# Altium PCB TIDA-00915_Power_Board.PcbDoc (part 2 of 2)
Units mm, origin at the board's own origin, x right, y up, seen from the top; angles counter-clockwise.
Board outline 80 x 46 mm, 3 copper layers (Top Layer, Signal Layer 1, Base Aluminium), stack 1.964 mm thick; 95 components, 53 nets, 450 pads, 406 vias.
Unrouted connection lines stored in the file: 2.
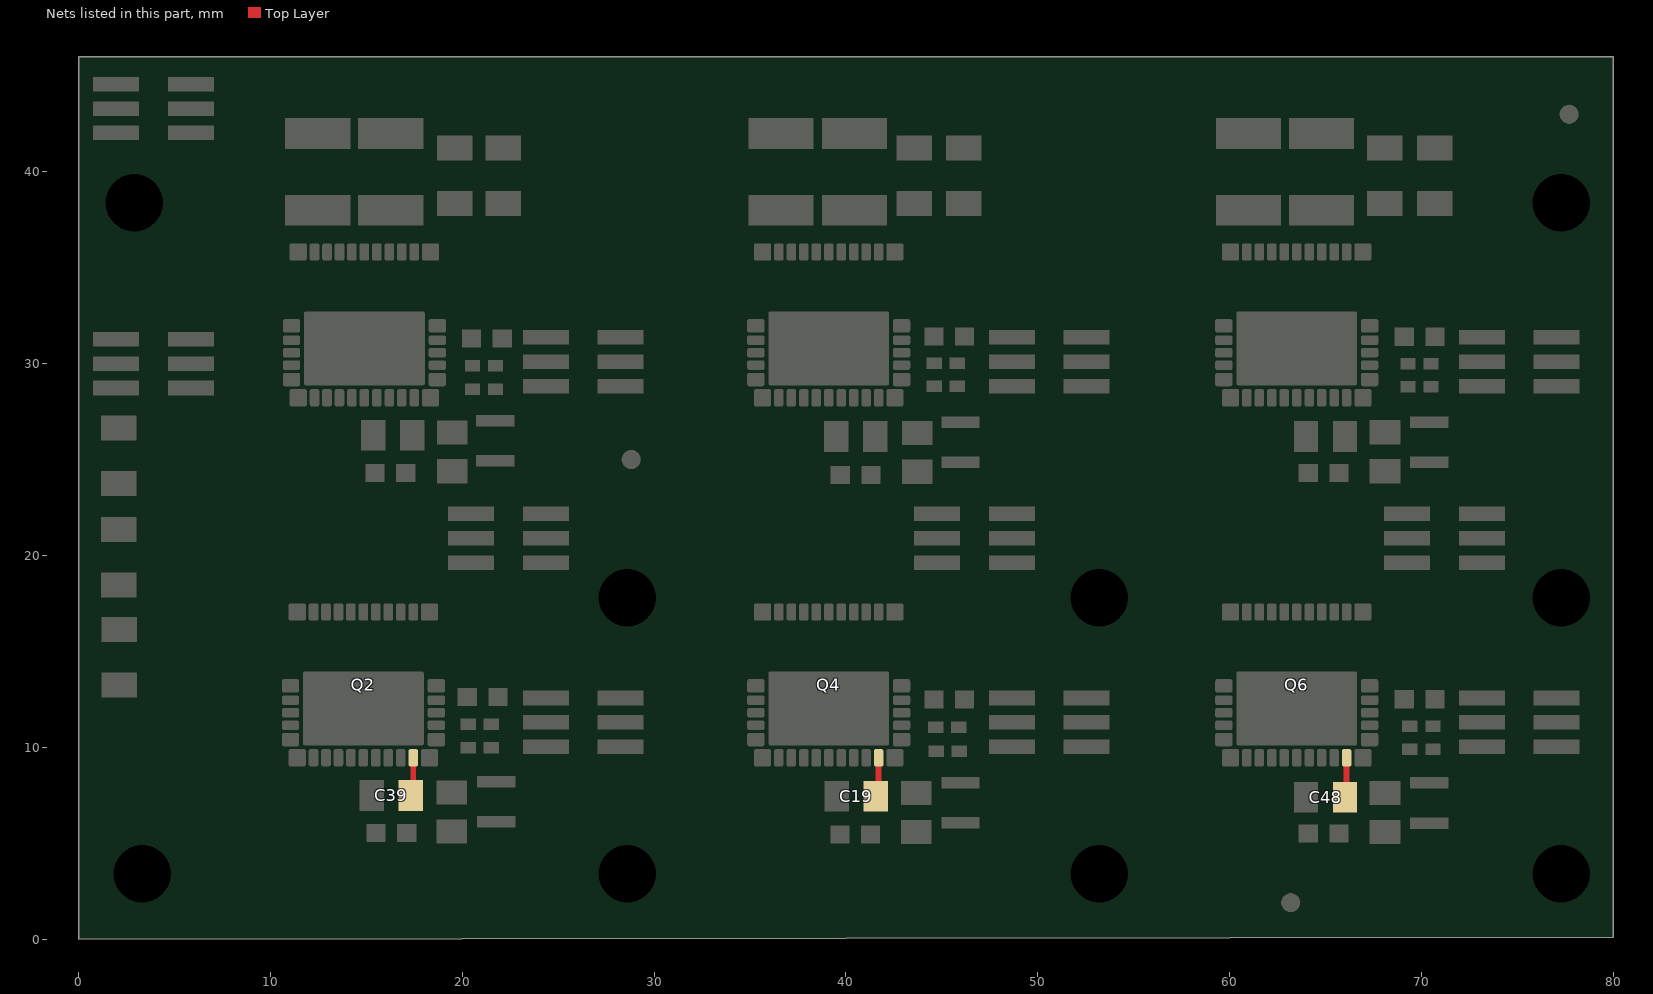
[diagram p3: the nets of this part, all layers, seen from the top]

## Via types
v1: diameter 0.559, hole 0.305, Top Layer to Signal Layer 1, 282 vias
v2: diameter 0.61, hole 0.305, Top Layer to Signal Layer 1, 118 vias
v3: diameter 0.8, hole 0.4, Top Layer to Signal Layer 1, 6 vias

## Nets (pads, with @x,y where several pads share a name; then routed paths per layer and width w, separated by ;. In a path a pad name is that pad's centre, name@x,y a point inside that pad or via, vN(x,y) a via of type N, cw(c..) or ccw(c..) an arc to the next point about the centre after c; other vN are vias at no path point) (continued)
VM12V_L_U: C39.1 Q2.26 | length 2
  Top Layer w0.203: C39.1@17.316,7.491 C39.1@17.439,7.614
  Top Layer w0.305: C39.1@17.439,7.614 Q2.26@17.439,9.452
VM12V_L_V: C19.1 Q4.26 | length 2.1
  Top Layer w0.305: C19.1@41.549,7.441 41.7,7.591 Q4.26@41.7,9.452
VM12V_L_W: C48.1 Q6.26 | length 2.1
  Top Layer w0.305: C48.1@66.016,7.4 66.1,7.484 Q6.26@66.1,9.452
pads on no net: FID1.1 FID2.1 FID3.1 Q1.33@12.512,29.908 Q1.33@12.512,31.708 Q1.33@13.702,29.908 Q1.33@13.702,31.708 Q1.33@14.892,29.908 Q1.33@14.892,31.708 Q1.33@16.082,29.908 Q1.33@16.082,31.708 Q1.33@17.272,29.908 Q1.33@17.272,31.708 Q2.33@12.459,11.138 Q2.33@12.459,12.938 Q2.33@13.649,11.138 Q2.33@13.649,12.938 Q2.33@14.839,11.138 Q2.33@14.839,12.938 Q2.33@16.029,11.138 Q2.33@16.029,12.938 Q2.33@17.219,11.138 Q2.33@17.219,12.938 Q3.33@36.72,29.908 Q3.33@36.72,31.708 Q3.33@37.91,29.908 Q3.33@37.91,31.708 Q3.33@39.1,29.908 Q3.33@39.1,31.708 Q3.33@40.29,29.908 Q3.33@40.29,31.708 Q3.33@41.48,29.908 Q3.33@41.48,31.708 Q4.33@36.72,11.138 Q4.33@36.72,12.938 Q4.33@37.91,11.138 Q4.33@37.91,12.938 Q4.33@39.1,11.138 Q4.33@39.1,12.938 Q4.33@40.29,11.138 Q4.33@40.29,12.938 Q4.33@41.48,11.138 Q4.33@41.48,12.938 Q5.33@61.12,29.908 Q5.33@61.12,31.708 Q5.33@62.31,29.908 Q5.33@62.31,31.708 Q5.33@63.5,29.908 Q5.33@63.5,31.708 Q5.33@64.69,29.908 Q5.33@64.69,31.708 Q5.33@65.88,29.908 Q5.33@65.88,31.708 Q6.33@61.12,11.138 Q6.33@61.12,12.938 Q6.33@62.31,11.138 Q6.33@62.31,12.938 Q6.33@63.5,11.138 Q6.33@63.5,12.938 Q6.33@64.69,11.138 Q6.33@64.69,12.938 Q6.33@65.88,11.138 Q6.33@65.88,12.938

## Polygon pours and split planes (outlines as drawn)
PHASEW on Top Layer "TOP_LAYER_PHASEW_P170" (solid, remove dead copper, pour order 170): 71.619,29.716 ccw(c71.619,29.553) 71.455,29.553 71.455,28.561 cw(c71.295,28.561) 71.295,28.4 70.894,28.396 cw(c70.879,28.471) 70.879,28.395 70.523,28.395 cw(c70.523,28.674) 70.244,28.674 70.244,31.524 cw(c70.468,31.524) 70.468,31.748 71.082,31.748 cw(c71.082,31.468) 71.361,31.468 71.361,30.591 ccw(c71.551,30.591) 71.551,30.402 71.92,30.402 cw(c71.92,30.164) 72.158,30.164 72.158,29.905 cw(c71.969,29.905) 71.969,29.716
PHASEV on Top Layer "TOP_LAYER_PHASEV_P168" (solid, remove dead copper, pour order 168): 47.219,29.716 ccw(c47.219,29.553) 47.055,29.553 47.055,28.561 cw(c46.895,28.561) 46.895,28.4 46.494,28.396 cw(c46.479,28.471) 46.479,28.395 46.123,28.395 cw(c46.123,28.674) 45.844,28.674 45.844,31.524 cw(c46.068,31.524) 46.068,31.748 46.682,31.748 cw(c46.682,31.468) 46.961,31.468 46.961,30.591 ccw(c47.151,30.591) 47.151,30.402 47.52,30.402 cw(c47.52,30.164) 47.758,30.164 47.758,29.905 cw(c47.569,29.905) 47.569,29.716
HVBUS_RTN on Top Layer "TOP_LAYER_HVBUS_RTN_P162" (solid, remove dead copper, pour order 162): 59.216,4.087 ccw(c59.803,4.087) 59.803,3.501 71.208,3.501 ccw(c71.203,4.03) 71.732,4.034 ccw(c71.37,4.106) 71.739,4.106 71.739,5.873 ccw(c71.395,5.873) 71.395,6.217 67.409,6.217 ccw(c67.409,6.09) 67.283,6.09 67.283,4.869 cw(c67.068,4.869) 67.068,4.654 64.737,4.654 cw(c64.737,5.006) 64.384,5.006 64.384,8.448 cw(c64.644,8.448) 64.644,8.708 ccw(c64.644,8.837) 64.774,8.837 64.774,13.477 ccw(c64.344,13.477) 64.344,13.906 56.892,13.906 ccw(c56.892,13.637) 56.622,13.637 56.622,8.963 ccw(c56.794,8.963) 56.794,8.792 59.089,8.792 cw(c59.089,8.664) 59.216,8.664
PHASEW on Top Layer "TOP_LAYER_PHASEW_P158" (solid, remove dead copper, pour order 158): 63.75,22.76 cw(c63.75,23.066) 63.445,23.066 63.445,28.894 cw(c63.553,28.901) 63.546,29.01 64.635,29.01 cw(c64.635,28.773) 64.873,28.773 64.873,28.017 cw(c64.669,28.017) 64.669,27.813 64.531,27.813 ccw(c64.531,27.597) 64.314,27.597 64.314,23.841 ccw(c64.627,23.841) 64.627,23.528 67.236,23.528 ccw(c67.236,23.819) 67.528,23.819 67.528,24.758 cw(c67.744,24.758) 67.744,24.975 71.611,24.975 cw(c71.611,24.868) 71.718,24.868 71.718,23.152 cw(c71.326,23.152) 71.326,22.76
PHASEW on Top Layer "TOP_LAYER_PHASEW_P156" (solid, remove dead copper, pour order 156): 62.99,27.76 ccw(c62.99,27.559) 62.789,27.559 62.789,22.891 ccw(c63.185,22.891) 63.185,22.496 73.819,22.496 cw(c73.819,22.365) 73.95,22.365 73.95,18.741 cw(c73.8,18.741) 73.8,18.591 69.928,18.596 cw(c69.916,18.795) 69.915,18.596 67.805,18.596 ccw(c67.805,18.367) 67.576,18.367 67.568,16.688 cw(c67.468,16.696) 67.468,16.596 60.168,16.596 59.507,16.609 cw(c59.507,16.863) 59.253,16.863 59.253,32.561 cw(c59.421,32.561) 59.421,32.728 61.423,32.728 ccw(c61.445,32.728) 61.445,32.706 63.592,32.706 cw(c63.594,32.538) 63.762,32.54 63.762,27.871 cw(c63.651,27.871) 63.651,27.76
PHASEV on Top Layer "TOP_LAYER_PHASEV_P154" (solid, remove dead copper, pour order 154): 39.924,27.534 cw(c40.138,27.534) 40.138,27.748 40.665,27.748 ccw(c40.665,27.798) 40.716,27.798 40.716,28.934 ccw(c40.639,28.934) 40.639,29.01 40.246,29.01 38.954,29.01 ccw(c38.954,28.91) 38.854,28.91 38.854,23.249 ccw(c39.343,23.249) 39.343,22.76 46.937,22.76 ccw(c46.937,23.152) 47.329,23.152 47.329,24.868 ccw(c47.222,24.868) 47.222,24.975 43.355,24.975 ccw(c43.355,24.758) 43.138,24.758 43.138,23.819 cw(c42.847,23.819) 42.847,23.528 40.237,23.528 cw(c40.237,23.841) 39.924,23.841
HVBUS_RTN on Top Layer "TOP_LAYER_HVBUS_RTN_P148" (solid, remove dead copper, pour order 148): 32.23,13.957 ccw(c32.23,13.863) 32.136,13.863 32.136,9.031 ccw(c32.346,9.031) 32.346,8.822 34.578,8.822 cw(c34.578,8.643) 34.756,8.643 34.756,4.387 ccw(c35.356,4.387) 35.356,3.787 46.909,3.787 ccw(c46.909,4.157) 47.279,4.157 47.279,5.923 ccw(c46.935,5.923) 46.935,6.267 42.949,6.267 ccw(c42.949,6.141) 42.823,6.141 42.823,4.92 cw(c42.608,4.92) 42.608,4.704 40.277,4.704 cw(c40.277,5.057) 39.924,5.057 39.924,8.499 cw(c40.184,8.499) 40.184,8.759 ccw(c40.184,8.888) 40.314,8.888 40.314,13.527 ccw(c39.884,13.527) 39.884,13.957
PHASEV on Top Layer "TOP_LAYER_PHASEV_P146" (solid, remove dead copper, pour order 146): 38.324,27.79 ccw(c38.324,27.743) 38.278,27.743 38.278,22.841 ccw(c38.623,22.841) 38.623,22.496 49.504,22.496 cw(c49.504,22.3) 49.7,22.3 49.7,18.8 cw(c49.5,18.8) 49.5,18.6 45.366,18.596 cw(c45.354,18.795) 45.354,18.596 43.243,18.596 ccw(c43.243,18.367) 43.014,18.367 43.006,16.688 cw(c42.906,16.696) 42.906,16.596 35.137,16.596 cw(c35.137,16.863) 34.869,16.863 34.869,32.471 cw(c35.122,32.471) 35.122,32.724 35.26,32.724 cw(c35.305,32.498) 35.305,32.728 36.861,32.728 ccw(c36.883,32.728) 36.883,32.706 39.03,32.706 cw(c39.032,32.538) 39.2,32.54 39.2,28.295 39.2,27.9 cw(c39.091,27.9) 39.091,27.79
PHASEU on Top Layer "TOP_LAYER_PHASEU_P132" (solid, remove dead copper, pour order 132): 15.536,27.568 cw(c15.75,27.568) 15.75,27.781 16.276,27.781 ccw(c16.276,27.832) 16.327,27.832 16.327,28.968 ccw(c16.251,28.968) 16.251,29.044 15.857,29.044 14.566,29.044 ccw(c14.566,28.943) 14.465,28.943 14.465,23.283 ccw(c14.955,23.283) 14.955,22.794 22.548,22.794 ccw(c22.548,23.186) 22.94,23.186 22.94,24.901 ccw(c22.833,24.901) 22.833,25.008 18.966,25.008 ccw(c18.966,24.792) 18.75,24.792 18.75,23.853 cw(c18.458,23.853) 18.458,23.562 15.849,23.562 cw(c15.849,23.874) 15.536,23.874
HVBUS_RTN on Top Layer "TOP_LAYER_HVBUS_RTN_P058" (solid, remove dead copper, pour order 58): 70.6,12.975 ccw(c70.6,12.751) 70.376,12.751 70.376,9.902 ccw(c70.656,9.902) 70.656,9.622 71.011,9.622 ccw(c71.011,9.698) 71.087,9.698 71.087,10.714 cw(c71.316,10.714) 71.316,10.943 72.101,10.943 ccw(c72.101,11.132) 72.29,11.132 72.29,11.391 ccw(c72.053,11.391) 72.053,11.629 71.683,11.629 cw(c71.683,11.818) 71.494,11.818 71.494,12.696 ccw(c71.214,12.696) 71.214,12.975
HVBUS_RTN on Top Layer "TOP_LAYER_HVBUS_RTN_P052" (solid, remove dead copper, pour order 52): 46.06,12.953 ccw(c46.06,12.73) 45.837,12.73 45.837,9.88 ccw(c46.116,9.88) 46.116,9.601 46.472,9.601 ccw(c46.472,9.677) 46.548,9.677 46.548,10.693 cw(c46.776,10.693) 46.776,10.921 47.562,10.921 ccw(c47.562,11.111) 47.751,11.111 47.751,11.369 ccw(c47.513,11.369) 47.513,11.607 47.144,11.607 cw(c47.144,11.797) 46.954,11.797 46.954,12.674 ccw(c46.675,12.674) 46.675,12.953
HVBUS_RTN on Top Layer "HVBUS_RTN_MAIN" (solid, remove dead copper, pour order 38): 71.474,45 cw(c71.474,44.871) 71.602,44.871 71.602,41.152 cw(c71.45,41.152) 71.45,41 69.759,41.006 cw(c69.7,41.3) 69.7,41 10.1,41 cw(c10.1,41.2) 9.9,41.2 9.9,41.5 ccw(c9.7,41.5) 9.7,41.7 1.2,41.7 cw(c1.2,42) 0.9,42 0.9,44.5 cw(c1.4,44.5) 1.4,45 9.8,45
HVBUS on Top Layer "HVBUS_MAIN" (solid, remove dead copper, pour order 40): 8.971,35.5 ccw(c8.971,35.254) 8.726,35.254 8.726,28.793 cw(c8.469,28.795) 8.467,28.538 cw(c8.4,29.222) 8.4,28.535 1.15,28.535 cw(c1.15,28.885) 0.8,28.885 0.8,34.298 cw(c1.524,34.298) 1.524,35.022 6.063,35.022 ccw(c6.063,35.459) 6.5,35.459 6.5,38.4 cw(c6.798,38.398) 6.8,38.696 7.861,38.696 cw(c7.899,38.508) 7.9,38.7 69.663,38.7 69.663,38.696 71.404,38.696 cw(c71.404,38.524) 71.411,38.696 cw(c71.411,38.461) 71.646,38.461 71.646,35.597 cw(c71.549,35.597) 71.549,35.5
PHASEU on Top Layer "TOP_LAYER_PHASEU_P044" (solid, remove dead copper, pour order 44): 23.011,29.716 ccw(c23.011,29.553) 22.847,29.553 22.847,28.561 cw(c22.687,28.561) 22.687,28.4 22.286,28.396 cw(c22.271,28.471) 22.271,28.395 21.915,28.395 cw(c21.915,28.674) 21.636,28.674 21.636,31.524 cw(c21.86,31.524) 21.86,31.748 22.474,31.748 cw(c22.474,31.468) 22.753,31.468 22.753,30.591 ccw(c22.943,30.591) 22.943,30.402 23.312,30.402 cw(c23.312,30.164) 23.55,30.164 23.55,29.905 cw(c23.361,29.905) 23.361,29.716
PHASEU on Top Layer "TOP_LAYER_PHASEU_P120" (solid, remove dead copper, pour order 120): 24.7,18.6 24.75,18.6 ccw(c24.75,19) 25.15,19 25.15,22.209 ccw(c24.859,22.209) 24.86,22.5 14.15,22.5 cw(c14.15,22.65) 14,22.65 14,27.572 cw(c14.4,27.572) 14.4,27.972 ccw(c14.4,28.299) 14.727,28.299 14.727,32.544 ccw(c14.559,32.542) 14.557,32.71 12.41,32.71 cw(c12.41,32.733) 12.388,32.733 10.833,32.733 ccw(c10.833,32.5) 10.6,32.5 10.6,16.813 ccw(c10.813,16.813) 10.813,16.6 18.433,16.6 ccw(c18.433,16.7) 18.533,16.692 18.541,18.371 cw(c18.77,18.371) 18.77,18.6 20.73,18.6
HVBUS_RTN on Top Layer "TOP_LAYER_HVBUS_RTN_P126" (solid, remove dead copper, pour order 126): 22.738,11.016 ccw(c22.738,10.853) 22.574,10.853 22.574,9.861 cw(c22.414,9.861) 22.414,9.7 22.013,9.696 cw(c21.998,9.771) 21.998,9.695 21.642,9.695 cw(c21.642,9.974) 21.363,9.974 21.363,12.824 cw(c21.587,12.824) 21.587,13.048 22.201,13.048 cw(c22.201,12.768) 22.48,12.768 22.48,11.891 ccw(c22.67,11.891) 22.67,11.702 23.039,11.702 cw(c23.039,11.464) 23.277,11.464 23.277,11.205 cw(c23.088,11.205) 23.088,11.016
HVBUS_RTN on Top Layer "TOP_LAYER_HVBUS_RTN_P130" (solid, remove dead copper, pour order 130): 10.582,3.882 ccw(c10.947,3.882) 10.947,3.516 22.421,3.516 ccw(c22.421,4.2) 23.105,4.2 23.105,5.967 ccw(c22.761,5.967) 22.761,6.311 18.775,6.311 ccw(c18.775,6.184) 18.649,6.184 18.649,4.963 cw(c18.434,4.963) 18.434,4.748 16.102,4.748 cw(c16.102,5.1) 15.75,5.1 15.75,8.542 cw(c16.01,8.542) 16.01,8.802 ccw(c16.01,8.931) 16.139,8.931 16.139,13.571 ccw(c15.71,13.571) 15.71,14 7.771,14 ccw(c7.771,13.829) 7.6,13.829 7.6,8.906 ccw(c7.82,8.906) 7.82,8.686 10.438,8.686 cw(c10.438,8.542) 10.582,8.542
PHASEU on Signal Layer 1 "SIGNAL_LAYER_1_PHASEU_P128" (solid, remove dead copper, pour order 128): 29.624,33.6 cw(c29.624,33.43) 29.794,33.43 29.794,22.661 cw(c29.616,22.661) 29.616,22.483 28.715,22.527 15.362,22.527 14.6,22.53 cw(c14.6,22.888) 14.242,22.888 14.242,28.222 cw(c14.376,28.222) 14.376,28.356 18.6,28.356 ccw(c18.6,28.698) 18.942,28.698 18.942,32.227 18.942,33.5 cw(c19.042,33.5) 19.042,33.6
PHASEU on Signal Layer 1 "SIGNAL_LAYER_1_PHASEU_P116" (solid, remove dead copper, pour order 116): 14.947,32.695 14.608,32.695 ccw(c14.608,32.409) 14.322,32.409 14.322,28.978 ccw(c14.625,28.978) 14.625,28.674 15.002,28.674 ccw(c15.002,28.7) 15.028,28.7 18.479,28.7 ccw(c18.478,28.974) 18.752,28.974 18.752,32.409 ccw(c18.461,32.409) 18.461,32.7 15,32.7 ccw(c15,32.428)
no net on Signal Layer 1 "SIGNAL_LAYER_1_NONET_P068" (solid, remove dead copper, pour order 68): 21.096,44.96
no net on Signal Layer 1 "SIGNAL_LAYER_1_NONET_P088" (solid, remove dead copper, pour order 88): 12.828,28.29
no net on Signal Layer 1 "SIGNAL_LAYER_1_NONET_P090" (solid, remove dead copper, pour order 90): 13.628,28.311
no net on Signal Layer 1 "SIGNAL_LAYER_1_NONET_P096" (solid, remove dead copper, pour order 96): 19.182,11.9 19.241,11.959 19.241,12
PHASEV on Signal Layer 1 "SIGNAL_LAYER_1_PHASEV_P134" (solid, remove dead copper, pour order 134): 39.204,32.746 38.865,32.746 ccw(c38.865,32.46) 38.579,32.46 38.579,29.029 ccw(c38.882,29.029) 38.882,28.725 39.259,28.725 ccw(c39.259,28.751) 39.285,28.751 42.736,28.751 ccw(c42.735,29.025) 43.009,29.025 43.009,32.46 ccw(c42.718,32.46) 42.718,32.751 39.257,32.751 ccw(c39.257,32.479)
PHASEV on Signal Layer 1 "SIGNAL_LAYER_1_PHASEV_P136" (solid, remove dead copper, pour order 136): 38.734,28.254 ccw(c38.734,28.12) 38.601,28.12 38.601,22.787 ccw(c38.959,22.787) 38.959,22.429 39.721,22.426 53.144,22.426 ccw(c53.144,23.041) 53.759,23.041 53.759,32.326 ccw(c53.559,32.326) 53.725,32.437 53.725,33.145 ccw(c53.372,33.145) 53.372,33.498 43.401,33.498 ccw(c43.401,33.398) 43.301,33.398 43.301,32.126 43.301,28.596 cw(c42.959,28.596) 42.959,28.254
PHASEW on Signal Layer 1 "SIGNAL_LAYER_1_PHASEW_P140" (solid, remove dead copper, pour order 140): 63.639,32.746 63.3,32.746 ccw(c63.3,32.46) 63.014,32.46 63.014,29.029 ccw(c63.317,29.029) 63.317,28.725 63.694,28.725 ccw(c63.694,28.751) 63.72,28.751 67.171,28.751 ccw(c67.17,29.025) 67.444,29.025 67.444,32.46 ccw(c67.153,32.46) 67.153,32.751 63.692,32.751 ccw(c63.692,32.479)
HVBUS_RTN on Signal Layer 1 "SIGNAL_LAYER_1_HVBUS_RTN_P142" (solid, remove dead copper, pour order 142): 36.9,16.096 ccw(c37.5,16.096) 37.5,15.497 42.023,15.497 cw(c42.042,14.981) 42.558,15 42.558,10.349 cw(c42.258,10.349) 42.258,10.049 32.634,10.049 cw(c32.65,10.563) 32.136,10.578 32.136,44.247 cw(c32.736,44.247) 32.736,44.846 46.8,44.846 cw(c46.8,44.178) 47.468,44.178 47.468,36.922 cw(c47.201,36.922) 47.2,36.654 43.627,36.654 ccw(c43.627,36.219) 43.192,36.219 43.192,35.849 cw(c42.761,35.849) 42.761,35.418 37.269,35.418 ccw(c37.269,35.049) 36.9,35.049
HVBUS_RTN on Signal Layer 1 "SIGNAL_LAYER_1_HVBUS_RTN_P122" (solid, remove dead copper, pour order 122): 12.7,15.869 ccw(c13.069,15.869) 13.069,15.5 18.003,15.5 cw(c17.985,15.128) 18.357,15.111 18.357,10.4 cw(c18.057,10.4) 18.057,10.1 8.098,10.1 cw(c8.088,10.588) 7.6,10.579 7.6,44.675 cw(c7.822,44.675) 7.822,44.897 22.6,44.897 cw(c22.6,44.229) 23.268,44.229 23.268,36.973 cw(c23,36.973) 23,36.705 19.427,36.705 ccw(c19.427,36.27) 18.992,36.27 18.992,35.9 cw(c18.561,35.9) 18.561,35.469 13.069,35.469 ccw(c13.069,35.1) 12.7,35.1
HVBUS_RTN on Signal Layer 1 "SIGNAL_LAYER_1_HVBUS_RTN_P150" (solid, pour order 150): 54.4,7.4 cw(c54.2,7.4) 54.2,7.2 50.227,7.2 ccw(c50.227,6.8) 49.827,6.8 49.827,4.651 cw(c49,4.651) 49,3.824 39.598,3.824 35.317,3.827 32.509,3.827 cw(c32.509,4.2) 32.136,4.2 32.136,10.621 cw(c32.532,10.621) 32.532,11.017 41.917,11.017 41.917,13.628 cw(c42.193,13.629) 41.917,13.631 41.917,14.361 cw(c42.134,14.361) 42.134,14.577 54.306,14.577 cw(c54.306,14.483) 54.4,14.483
HVBUS_RTN on Signal Layer 1 "SIGNAL_LAYER_1_HVBUS_RTN_P152" (solid, pour order 152): 29.77,7.57 cw(c29.4,7.57) 29.4,7.2 24.95,7.2 ccw(c24.95,6.6) 24.35,6.6 cw(c24.35,6.55) 24.4,6.55 24.4,3.7 cw(c24.216,3.7) 24.216,3.516 24,3.513 15.064,3.513 10.782,3.516 7.975,3.516 cw(c7.975,3.889) 7.602,3.889 7.602,10.311 cw(c7.998,10.311) 7.998,10.707 17.382,10.707 17.382,13.318 cw(c17.659,13.318) 17.382,13.321 17.382,14.482 cw(c17.6,14.482) 17.6,14.7 29.57,14.7 cw(c29.57,14.5) 29.77,14.5
PHASEW on Signal Layer 1 "SIGNAL_LAYER_1_PHASEW_P138" (solid, remove dead copper, pour order 138): 63.322,28.203 ccw(c63.322,28.07) 63.188,28.07 63.188,22.736 ccw(c63.546,22.736) 63.546,22.378 64.308,22.375 77.731,22.375 ccw(c77.731,22.99) 78.346,22.99 78.346,32.275 ccw(c78.146,32.275) 78.312,32.386 78.312,33.095 ccw(c77.959,33.095) 77.959,33.448 67.988,33.448 ccw(c67.988,33.348) 67.888,33.348 67.888,32.075 67.888,28.545 cw(c67.546,28.545) 67.546,28.203
HVBUS_RTN on Signal Layer 1 "SIGNAL_LAYER_1_HVBUS_RTN_P160" (solid, remove dead copper, pour order 160): 61.386,16.414 ccw(c62.2,16.414) 62.2,15.6 66.689,15.6 cw(c66.716,15.273) 67.043,15.3 67.043,10.451 cw(c66.743,10.451) 66.743,10.151 57.12,10.151 cw(c57.135,10.664) 56.622,10.68 56.622,44.348 cw(c57.221,44.348) 57.221,44.947 71.286,44.947 cw(c71.286,44.28) 71.954,44.28 71.954,37.024 cw(c71.686,37.024) 71.686,36.756 68.113,36.756 ccw(c68.113,36.321) 67.678,36.321 67.678,35.951 cw(c67.247,35.951) 67.247,35.52 61.755,35.52 ccw(c61.755,35.151) 61.386,35.151
HVBUS_RTN on Signal Layer 1 "SIGNAL_LAYER_1_HVBUS_RTN_P164" (solid, pour order 164): 78.6,8.191 cw(c77.9,8.191) 77.9,7.491 74.921,7.491 ccw(c74.921,6.5) 73.93,6.5 73.93,4.188 cw(c73.27,4.158) 73.3,3.498 64.084,3.498 59.803,3.501 56.995,3.501 cw(c56.995,3.874) 56.622,3.874 56.622,10.295 cw(c57.018,10.295) 57.018,10.691 66.403,10.691 66.403,13.302 cw(c66.679,13.302) 66.403,13.305 66.403,14.129 cw(c66.874,14.129) 66.874,14.6 78.483,14.6 cw(c78.483,14.483) 78.6,14.483

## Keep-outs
Keep-Out Layer:
  text ".Layer_Name" at -9.944,-51.406 h1.52

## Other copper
Top Layer:
  text ".Layer_Name" at -9.944,-51.406 h1.52
Base Aluminium:
  text ".Layer_Name" at -9.944,-51.406 h1.52

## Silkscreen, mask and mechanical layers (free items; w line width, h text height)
Top Overlay:
  circle w0.254: c2.9,38.4 r2.5
  circle w0.254: c53.2,3.4 r2.5
  circle w0.254: c28.6,3.4 r2.5
  circle w0.254: c77.3,3.4 r2.5
  circle w0.254: c77.3,38.4 r2.5
  circle w0.254: c77.3,17.8 r2.5
  circle w0.254: c53.2,17.8 r2.5
  circle w0.254: c28.6,17.8 r2.5
  circle w0.254: c3.3,3.4 r2.5
  text ".Layer_Name" at -9.944,-51.406 h1.52
Bottom Overlay:
  text ".Layer_Name" at -9.944,-51.406 h1.52
Top Paste:
  text ".Layer_Name" at -9.944,-51.406 h1.52
Bottom Paste:
  text ".Layer_Name" at -9.944,-51.406 h1.52
Top Solder:
  region: 55.773,38.45 55.773,36.95 58.573,36.95 58.573,38.45
  region: 31.5,38.5 31.5,37 34.3,37 34.3,38.5
  region: 7.088,38.5 7.088,36.1 10,36.1 10,38.5
  region: 56.775,12.88 56.775,8.88 59,8.88 59,12.88
  region: 32.375,12.95 32.375,8.95 34.6,8.95 34.6,12.95
  region: 7.975,12.9 7.975,8.9 10.2,8.9 10.2,12.9
  region: 59.911,22.1 59.911,19.1 64.924,19.1 64.924,22.1
  region: 35.479,22.1 35.479,19.1 40.492,19.1 40.492,22.1
  region: 11.339,22.1 11.339,19.1 16.353,19.1 16.353,22.1
  text ".Layer_Name" at -9.944,-51.406 h1.52
  text ".Layer_Name" at -9.944,-51.406 h1.52
Bottom Solder:
  text ".Layer_Name" at -9.944,-51.406 h1.52
Drill Guide:
  text ".Layer_Name" at -9.944,-51.406 h1.52
M1 Board Outline:
  lines w0.254: 0,0 80,0 80,46 0,46 0,0
M2 Board Dimensions:
  rectangle: -21.425,-39.76 -11.9,-36.585
  rectangle: -24.6,-36.585 -21.425,-33.41
  lines w0.178: -24.6,-36.585 0.8,-36.585 ; -21.425,-39.76 -21.425,-33.41 ; -18.25,-39.76 -18.25,-33.41 ; -11.9,-39.76 -11.9,-33.41 ; -5.55,-39.76 -5.55,-33.41 ; -24.6,-39.76 -24.6,-33.41 0.8,-33.41 0.8,-39.76 -24.6,-39.76
M3 3D STEP Top:
  text ".Layer_Name" at -9.944,-51.406 h1.52
M4 3D STEP Bottom:
  text ".Layer_Name" at -9.944,-51.406 h1.52
M5 Assembly Top:
  lines w0.254: -32.017,-53.226 135.623,-53.226 ; -32.017,-48.062 135.674,-48.062 ; -32.017,-42.897 -32.017,-58.391 69.71,-58.391 135.674,-58.391 135.674,-42.897 -32.004,-42.897 -32.004,-58.391 8.014,-58.391 ; 30.594,-58.391 30.594,-42.897 ; 62.776,-48.062 62.776,-42.897 ; 84.112,-48.062 84.112,-42.897 ; 99.911,-58.556 99.911,-53.404
  text "COMPONENTS MARKED 'DNP' SHOULD NOT BE POPULATED." at 4.699,-37.69 h1.52
  text "ASSEMBLY VARIANT:" at 4.686,-40.624 h1.52
  text ".VariantName" at 31.001,-40.624 h1.52
  text "PCB VIEWED FROM TOP SIDE" at -30.404,-46.254 h1.52
  text "BOARD #:" at 32.499,-46.254 h1.52
  text ".PRJ_Number" at 46.355,-46.254 h1.52
  text "REV:" at 67.805,-46.254 h1.52
  text ".PCB_Rev" at 75.209,-46.254 h1.52
  text "SVN REV:" at 89.09,-46.254 h1.52
  text ".VersionControl_RevNumber" at 101.943,-46.254 h1.52
  text "'.Layer_Name'" at -5.7,-51.3 h1.52
  text "TID #:" at 32.499,-51.419 h1.52
  text ".TID" at 46.355,-51.419 h1.52
  text "PLOT NAME =" at -30.404,-56.634 h1.52
  text ".plot_File_Name" at -9.944,-56.634 h1.52
  text "GENERATED    :" at 32.55,-56.634 h1.52
  text ".Print_Date" at 54.635,-56.634 h1.52
  text ".Print_Time" at 73.152,-56.634 h1.52
  text "TEXAS INSTRUMENTS" at 105.27,-56.634 h1.52
M6 Assembly Bottom:
  lines w0.254: -32.029,-48.074 135.661,-48.074 ; -31.979,-53.239 135.661,-53.239 ; 3.734,-58.569 3.734,-53.417 ; 19.533,-48.074 19.533,-42.91 ; 40.869,-48.074 40.869,-42.91 ; 73.05,-58.404 73.05,-42.91 ; 95.631,-58.404 135.649,-58.404 135.649,-42.91 -32.029,-42.91 -32.029,-58.404 33.934,-58.404 135.661,-58.404 135.661,-42.91
  text "COMPONENTS MARKED 'DNP' SHOULD NOT BE POPULATED." at 130.391,-37.677 h1.52
  text ".VariantName" at 103.873,-40.624 h1.52
  text "ASSEMBLY VARIANT:" at 130.264,-40.624 h1.52
  text ".VersionControl_RevNumber" at 1.702,-46.267 h1.52
  text "SVN REV:" at 14.554,-46.267 h1.52
  text ".PCB_Rev" at 28.435,-46.267 h1.52
  text "REV:" at 35.839,-46.267 h1.52
  text ".PRJ_Number" at 57.29,-46.267 h1.52
  text "BOARD #:" at 71.145,-46.267 h1.52
  text "PCB VIEWED FROM BOTTOM SIDE" at 134.048,-46.267 h1.52
  text ".TID" at 57.29,-51.431 h1.52
  text "TID #:" at 71.145,-51.431 h1.52
  text "'.Layer_Name'" at 101,-51.6 h1.52
  text "TEXAS INSTRUMENTS" at -1.626,-56.647 h1.52
  text ".Print_Time" at 30.493,-56.647 h1.52
  text ".Print_Date" at 49.009,-56.647 h1.52
  text "GENERATED    :" at 71.095,-56.647 h1.52
  text ".plot_File_Name" at 113.589,-56.647 h1.52
  text "PLOT NAME =" at 134.048,-56.647 h1.52
M9 Title Sheet:
  drawing of 57 lines, arcs and shapes, not listed
  text "1" at -5.808,174.527 h1.78
  text "2" at 57.582,174.527 h1.78
  text "3" at 120.811,174.527 h1.78
  text "4" at 184.48,174.527 h1.78
  text "5" at 247.955,174.527 h1.78
  text "6" at 311.582,174.527 h1.78
  text "A" at -35.179,145.495 h1.78
  text "A" at 340.741,145.495 h1.78
  text "B" at -35.179,85.043 h1.78
  text "B" at 340.741,85.043 h1.78
  text "C" at -35.179,24.718 h1.78
  text "C" at 340.741,24.718 h1.78
  text "PROJECT TITLE:" at 263.525,-22.551 h1.14
  text ".PRJ_Title" at 264.795,-25.938 h1.78
  text "DESIGNED FOR:" at 263.525,-30.197 h1.14
  text ".PRJ_Customer" at 264.795,-33.753 h1.78
  text "D" at -35.179,-35.48 h1.78
  text "D" at 340.741,-35.48 h1.78
  text "FILE NAME:" at 263.525,-37.817 h1.14
  text ".PCB_File_Name_No_Path" at 264.795,-40.865 h1.78
  text "Texas Instruments (TI) and/or its licensors do not warrant the accuracy or completeness of this specification" at 137.3,-44.976 h1.14
  text "ENGINEER:" at 263.525,-45.183 h1.14
  text "LAYOUT BY:" at 301.752,-45.183 h1.14
  text "or any information contained therein. TI and/or its licensors do not warrant that this design will meet" at 136.157,-47.837 h1.14
  text ".PRJ_Engineer" at 264.795,-49.12 h1.78
  text ".PCB_Layout" at 303.035,-49.12 h1.78
  text "the specifications, will be suitable for your application or fit for any particular purpose, or will operate in" at 136.157,-50.699 h1.14
  text "ALTIUM DESIGNER VERSION:" at 301.752,-53.057 h1.14
  text "an implementation. TI and/or its licensors do not warrant that the design is production worthy. You should" at 136.157,-53.561 h1.14
  text "completely validate and test your design implementation to confirm the system functionality for your application." at 137.3,-56.422 h1.14
  text ".print_Scale" at 264.795,-56.443 h1.78
  text ".Application_BuildNumber" at 303.035,-56.443 h1.78
  text "1" at -5.808,-61.693 h1.78
  text "2" at 57.582,-61.693 h1.78
  text "3" at 120.811,-61.693 h1.78
  text "4" at 184.48,-61.693 h1.78
  text "5" at 247.955,-61.693 h1.78
  text "6" at 311.582,-61.693 h1.78
M10 Fab Notes:
  drawing of 189 lines, arcs and shapes, not listed
  text "DESIGN INFORMATION" at 289.903,131.847 h1.52
  text "MIN. TRACK WIDTH:" at 273.531,128.491 h1.52
  text "8" at 301.376,128.491 h1.52
  text "MIL" at 305.307,128.491 h1.52
  text "MIN. CLEARANCE:" at 273.531,125.338 h1.52
  text "0.2" at 299.852,125.338 h1.52
  text "mm" at 305.307,125.338 h1.52
  text "MIN. VIA PAD SIZE:" at 273.531,122.185 h1.52
  text "24" at 300.614,122.185 h1.52
  text "MIL" at 305.307,122.185 h1.52
  text "0.05mm (2MIL)" at 291.184,118.886 h1.52
  text "MINIMUM ANNULAR RING" at 265.169,118.677 h1.52
  text "EXTERNAL" at 309.168,118.677 h1.52
  text "PER" at 270.249,115.88 h1.52
  text "IPC-D-275 CLASS 2 LEVEL C" at 275.837,115.88 h1.52
  text "MIL, HOLES" at 313.638,113.328 h1.52
  text "+/-" at 303.67,113.109 h1.52
  text "+/-" at 325.361,113.109 h1.52
  text "REGISTRATION TOLERANCES:" at 265.169,113.082 h1.52
  text "METAL" at 295.643,113.082 h1.52
  text "5" at 310.279,113.083 h1.52
  text "3" at 331.437,113.083 h1.52
  text "MIL" at 334.39,113.082 h1.52
  text "HOLE SIZE TOLERANCE (UNLESS OTHERWISE SPECIFIED):" at 265.169,110.585 h1.52
  text "+/-" at 325.361,110.512 h1.52
  text "3" at 331.437,110.485 h1.52
  text "MIL" at 334.39,110.485 h1.52
  text "MATERIAL:" at 263.27,106.989 h1.52
  text "FR-4 High Tg" at 288.326,103.724 h1.52
  text "FR-408" at 273.963,103.407 h1.52
  text "OTHER" at 311.758,103.407 h1.52
  text "62 MIL (1.6mm) +/-10%" at 282.094,99.774 h1.52
  text "THICKNESS:" at 265.169,99.565 h1.52
  text "OTHER" at 314.73,99.565 h1.52
  text "TOLERANCE:" at 265.169,96.052 h1.52
  text "ANSI IPC-6012 TYPE 3 CLASS 2" at 291.236,96.052 h1.52
  text "OTHER +/-" at 291.235,92.389 h1.52
  text "BOW & TWIST:" at 265.169,88.702 h1.52
  text "X" at 286.714,88.702 h1.52
  text "ANSI IPC-6012 TYPE 3 CLASS 2" at 291.236,88.702 h1.52
  text "OTHER +/-" at 291.235,84.976 h1.52
  text "DRILLING:" at 263.27,81.658 h1.52
  text "NC_DRILL FILES" at 307.999,78.986 h1.52
  text "REFERENCE:" at 265.169,78.886 h1.52
  text "X" at 281.863,78.884 h1.52
  text "AS SHOWN" at 286.384,78.886 h1.52
  text "X" at 304.748,78.886 h1.52
  text "OTHER" at 315.568,75.273 h1.52
  text "PTH COPPER THICKNESS:" at 265.161,75.183 h1.52
  text "X" at 294.097,75.183 h1.52
  text "20-30 um" at 297.348,75.183 h1.52
  text "BOARD FINISH:" at 263.27,71.434 h1.52
  text "SILKSCREEN:" at 267.213,68.637 h1.52
  text "X" at 291.54,68.637 h1.52
  text "TOP" at 294.512,68.637 h1.52
  text "X" at 304.494,68.637 h1.52
  text "BOTTOM" at 307.491,68.637 h1.52
  text "SILKSCREEN COLOR:" at 267.213,64.695 h1.52
  text "X" at 291.515,64.695 h1.52
  text "WHITE" at 294.512,64.695 h1.52
  text "OTHER" at 307.491,64.695 h1.52
  text "X" at 294.842,61.052 h1.52
  text "GREEN" at 297.839,61.052 h1.52
  text "OTHER" at 313.536,61.052 h1.52
  text "SOLDER RESIST COLOR:" at 267.213,60.877 h1.52
  text "X" at 294.842,57.134 h1.52
  text "MATTE" at 297.839,57.134 h1.52
  text "SEMI-GLOSS" at 313.525,57.117 h1.52
  text "IMMERSION GOLD (ENIG)" at 290.219,52.745 h1.52
  text "ENEPIG" at 324.193,52.562 h1.52
  text "SURFACE FINISH:" at 263.27,52.536 h1.52
  text "X" at 285.698,52.536 h1.52
  text "IMM. TIN/SILVER OR EQUIV" at 271.64,49.049 h1.52
  text "OTHER" at 307.999,48.949 h1.52
  text "ARRAY/PANEL:" at 263.27,45.002 h1.52
  text "CUT AND TRIM PER M1 BOARD OUTLINE" at 290.219,44.793 h1.52
  text "N.C. ROUTE" at 290.219,41.34 h1.52
  text "X" at 307.695,41.34 h1.52
  text "V. SCORE" at 312.216,41.34 h1.52
  text "CERTIFICATION:" at 263.27,38.06 h1.52
  text "MATERIALS AND WORKMANSHIP FOR ALL PCBS" at 281.685,38.06 h1.52
  text "TO MEET OR EXCEED THE REQUIREMENTS OF:" at 281.685,35.671 h1.52
  text "X" at 272.478,32.403 h1.52
  text "ANSI IPC-A-600F CLASS ->" at 275.729,32.403 h1.52
  text "X" at 317.588,32.403 h1.52
  text "2" at 320.382,32.403 h1.52
  text "1" at 312.381,32.365 h1.52
  text "3" at 329.373,32.365 h1.52
  text "X" at 293.102,28.652 h1.52
  text "RoHS" at 296.353,28.652 h1.52
  text "OTHER" at 312.721,28.652 h1.52
  text "PER ORDER" at 322.807,28.652 h1.52
  text "ALL BOARDS MUST MEET OR EXCEED UL94-V0 REQUIREMENTS." at 263.969,24.745 h1.52
  text "PCB MUST BEAR THE UL94V-0 UL REGISTERED MATERIAL ID NUMBER" at 263.969,21.797 h1.52
  text "NOTE:" at 108.214,18.101 h1.52
  text "ADDITIONAL REQUIREMENTS:" at 263.27,17.494 h1.52
  text "MICROSECTION:" at 265.169,14.773 h1.52
  text "YES" at 288.175,14.773 h1.52
  text "1)THIS IS NOT AN IMPEDANCE CONTROLLED BOARD." at 106.302,14.52 h1.52
  text "2)ALL VIAS ARE NONTENTED." at 106.133,11.598 h1.52
  text "REQUIRED" at 310.057,11.107 h1.52
  text "BARE BOARD ELEC. TEST:" at 265.169,11.034 h1.52
  text "NONE" at 298.335,11.034 h1.52
  text "X" at 307.06,11.034 h1.52
  text "PER ORDER" at 325.093,11.034 h1.52
  text "3)SELECTION OF DIELECRIC THICKNESS IS UP TO FAB VENDOR." at 106.233,8.698 h1.52
  text "XX MIL VIAS REQUIRE NON-CONDUCTIVE FILL AND PLANARIZE" at 269.44,5.828 h1.5
  text "4)COPPER THICKNESS SHOULD BE 2 OZ." at 105.706,5.725 h1.52
  text "XX MIL VIAS REQUIRE CONDUCTIVE FILL AND PLANARIZE" at 269.643,3.187 h1.52
  text "OUTER XX MIL TRACES REQUIRE 50 OHM SINGLE-ENDED IMPEDANCE" at 269.618,-0.963 h1.47
  text "LAYER 2 & 3 (INNER LAYERS) XX MIL WIDE, XX MIL SPACE / TRACES REQUIRE 100 OHM DIFFERENTIAL IMPEDANCE" at 269.415,-6.95 h1.52
M11 Gerber Information:
  lines w0.254: -32.017,-53.226 135.623,-53.226 ; -32.017,-48.062 135.674,-48.062 ; -32.017,-42.897 -32.017,-58.391 69.71,-58.391 135.674,-58.391 135.674,-42.897 -32.004,-42.897 -32.004,-58.391 8.014,-58.391 ; 30.594,-58.391 30.594,-42.897 ; 62.776,-48.062 62.776,-42.897 ; 84.112,-48.062 84.112,-42.897 ; 99.911,-58.556 99.911,-53.404
  text "ALL ARTWORK VIEWED FROM TOP SIDE" at -30.404,-46.254 h1.52
  text "BOARD #:" at 32.499,-46.254 h1.52
  text ".PRJ_Number" at 46.355,-46.254 h1.52
  text "REV:" at 67.805,-46.254 h1.52
  text ".PCB_Rev" at 75.209,-46.254 h1.52
  text "SVN REV:" at 89.09,-46.254 h1.52
  text ".VersionControl_RevNumber" at 101.943,-46.254 h1.52
  text "LAYER NAME =" at -30.404,-51.406 h1.52
  text "TID #:" at 32.499,-51.419 h1.52
  text ".TID" at 46.355,-51.419 h1.52
  text "PLOT NAME =" at -30.404,-56.634 h1.52
  text ".plot_File_Name" at -9.944,-56.634 h1.52
  text "GENERATED    :" at 32.55,-56.634 h1.52
  text ".Print_Date" at 54.635,-56.634 h1.52
  text ".Print_Time" at 73.152,-56.634 h1.52
  text "TEXAS INSTRUMENTS" at 105.27,-56.634 h1.52
M12 Stackup:
  drawing of 191 lines, arcs and shapes, not listed
  text "Layer" at 224.265,167.568 h1.52
  text "Name" at 234.677,167.568 h1.52
  text "Material" at 258.293,167.568 h1.52
  text "Thickness" at 280.131,167.568 h1.52
  text "Constant" at 296.636,167.568 h1.52
  text "Board Layer Stack" at 311.111,167.568 h1.52
  text "1" at 224.265,164.52 h1.52
  text "Top Overlay" at 234.677,164.52 h1.52
  text "2" at 224.265,161.472 h1.52
  text "Top Solder" at 234.677,161.472 h1.52
  text "Solder Resist" at 258.293,161.472 h1.52
  text "0.40mil" at 280.131,161.472 h1.52
  text "3.5" at 296.636,161.472 h1.52
  text "3" at 224.265,158.424 h1.52
  text "Top Layer" at 234.677,158.424 h1.52
  text "Copper" at 258.293,158.424 h1.52
  text "2.76mil" at 280.131,158.424 h1.52
  text "4" at 224.265,155.376 h1.52
  text "Dielectric1" at 234.677,155.376 h1.52
  text "Dielectric" at 258.293,155.376 h1.52
  text "5.98mil" at 280.131,155.376 h1.52
  text "3.4" at 296.636,155.376 h1.52
  text "5" at 224.265,152.328 h1.52
  text "Signal Layer 1" at 234.677,152.328 h1.52
  text "Copper" at 258.293,152.328 h1.52
  text "2.76mil" at 280.131,152.328 h1.52
  text "6" at 224.265,149.28 h1.52
  text "Dielectric 2" at 234.677,149.28 h1.52
  text "5.98mil" at 280.131,149.28 h1.52
  text "3.4" at 296.636,149.28 h1.52
  text "7" at 224.265,146.232 h1.52
  text "Base Aluminium" at 234.677,146.232 h1.52
  text "Copper" at 258.293,146.232 h1.52
  text "59.84mil" at 280.131,146.232 h1.52
M13 Component Bodies Top:
  text ".Layer_Name" at -9.944,-51.406 h1.52
M14 Component Bodies Bottom:
  text ".Layer_Name" at -9.944,-51.406 h1.52
M15 Courtyards Top:
  text ".Layer_Name" at -9.944,-51.406 h1.52
M16 Courtyards Bottom:
  text ".Layer_Name" at -9.944,-51.406 h1.52
Drill Drawing:
  circle w0.254: c111.262,49.687 r0.562
  lines w0.254: 110.7,51.655 111.824,51.655 111.824,52.78 110.7,52.78 110.7,51.655 ; 110.7,55.31 111.824,55.31 111.262,54.186 110.7,55.31
  lines w0.305: 109.664,48.366 190.525,48.366 ; 109.664,55.957 190.525,55.957 ; 117.682,45.835 117.682,58.487 ; 125.738,45.835 125.738,58.487 ; 141.53,45.835 141.53,58.487 ; 147.736,45.835 147.736,58.487 ; 156.889,45.835 156.889,58.487 ; 176.702,45.835 176.702,58.487 ; 109.664,45.835 190.525,45.835 190.525,58.487 109.664,58.487 109.664,45.835
  text "Symbol" at 111.183,56.716 h1.83
  text "Quantity" at 118.441,56.716 h1.83
  text "Finished Hole Size" at 126.497,56.716 h1.83
  text "Plated" at 142.289,56.716 h1.83
  text "Hole Type" at 148.495,56.716 h1.83
  text "Drill Layer Pair" at 157.648,56.716 h1.83
  text "Hole Tolerance" at 177.461,56.716 h1.83
  text "9" at 118.441,54.186 h1.52
  text "118.11mil (3.000mm)" at 126.497,54.186 h1.52
  text "NPTH" at 142.289,54.186 h1.52
  text "Round" at 148.495,54.186 h1.52
  text "Top Layer - Base Aluminium" at 157.648,54.186 h1.52
  text "400" at 118.441,51.655 h1.52
  text "12.00mil (0.305mm)" at 126.497,51.655 h1.52
  text "PTH" at 142.289,51.655 h1.52
  text "Round" at 148.495,51.655 h1.52
  text "Top Layer - Signal Layer 1" at 157.648,51.655 h1.52
  text "6" at 118.441,49.125 h1.52
  text "15.75mil (0.400mm)" at 126.497,49.125 h1.52
  text "PTH" at 142.289,49.125 h1.52
  text "Round" at 148.495,49.125 h1.52
  text "Top Layer - Signal Layer 1" at 157.648,49.125 h1.52
  text "415 Total" at 118.441,46.594 h1.52
  text "DRILL TOLERANCE" at 108.519,38.244 h1.52
  text "FOR 12MIL DRILL +0/- 12 MIL" at 110.322,32.96 h1.52
  text "FOR 15.75MIL DRILL +0/- 15.75 MIL" at 110.703,30.09 h1.52
  text "FOR PTH +/- 3 MIL" at 110.576,26.991 h1.52
  text ".Layer_Name" at -9.944,-51.406 h1.52
M17 Embedded Cavity:
  text ".Layer_Name" at -9.944,-51.406 h1.52
M18 Embedded Assembly:
  text ".Layer_Name" at -9.944,-51.406 h1.52
M19 Embedded Keepout:
  text ".Layer_Name" at -9.944,-51.406 h1.52

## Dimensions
0,46 to 0,0 on M2 Board Dimensions
0,46 to 80,46 on M2 Board Dimensions
-24.6,-39.76 to 0.8,-39.76 on M2 Board Dimensions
